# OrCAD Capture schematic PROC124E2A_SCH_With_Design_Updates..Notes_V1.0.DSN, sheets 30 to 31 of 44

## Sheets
30 29. JTAG 20 PIN cTI CONNECTOR: size C; title: JTAG 20 PIN cTI CONNECTOR
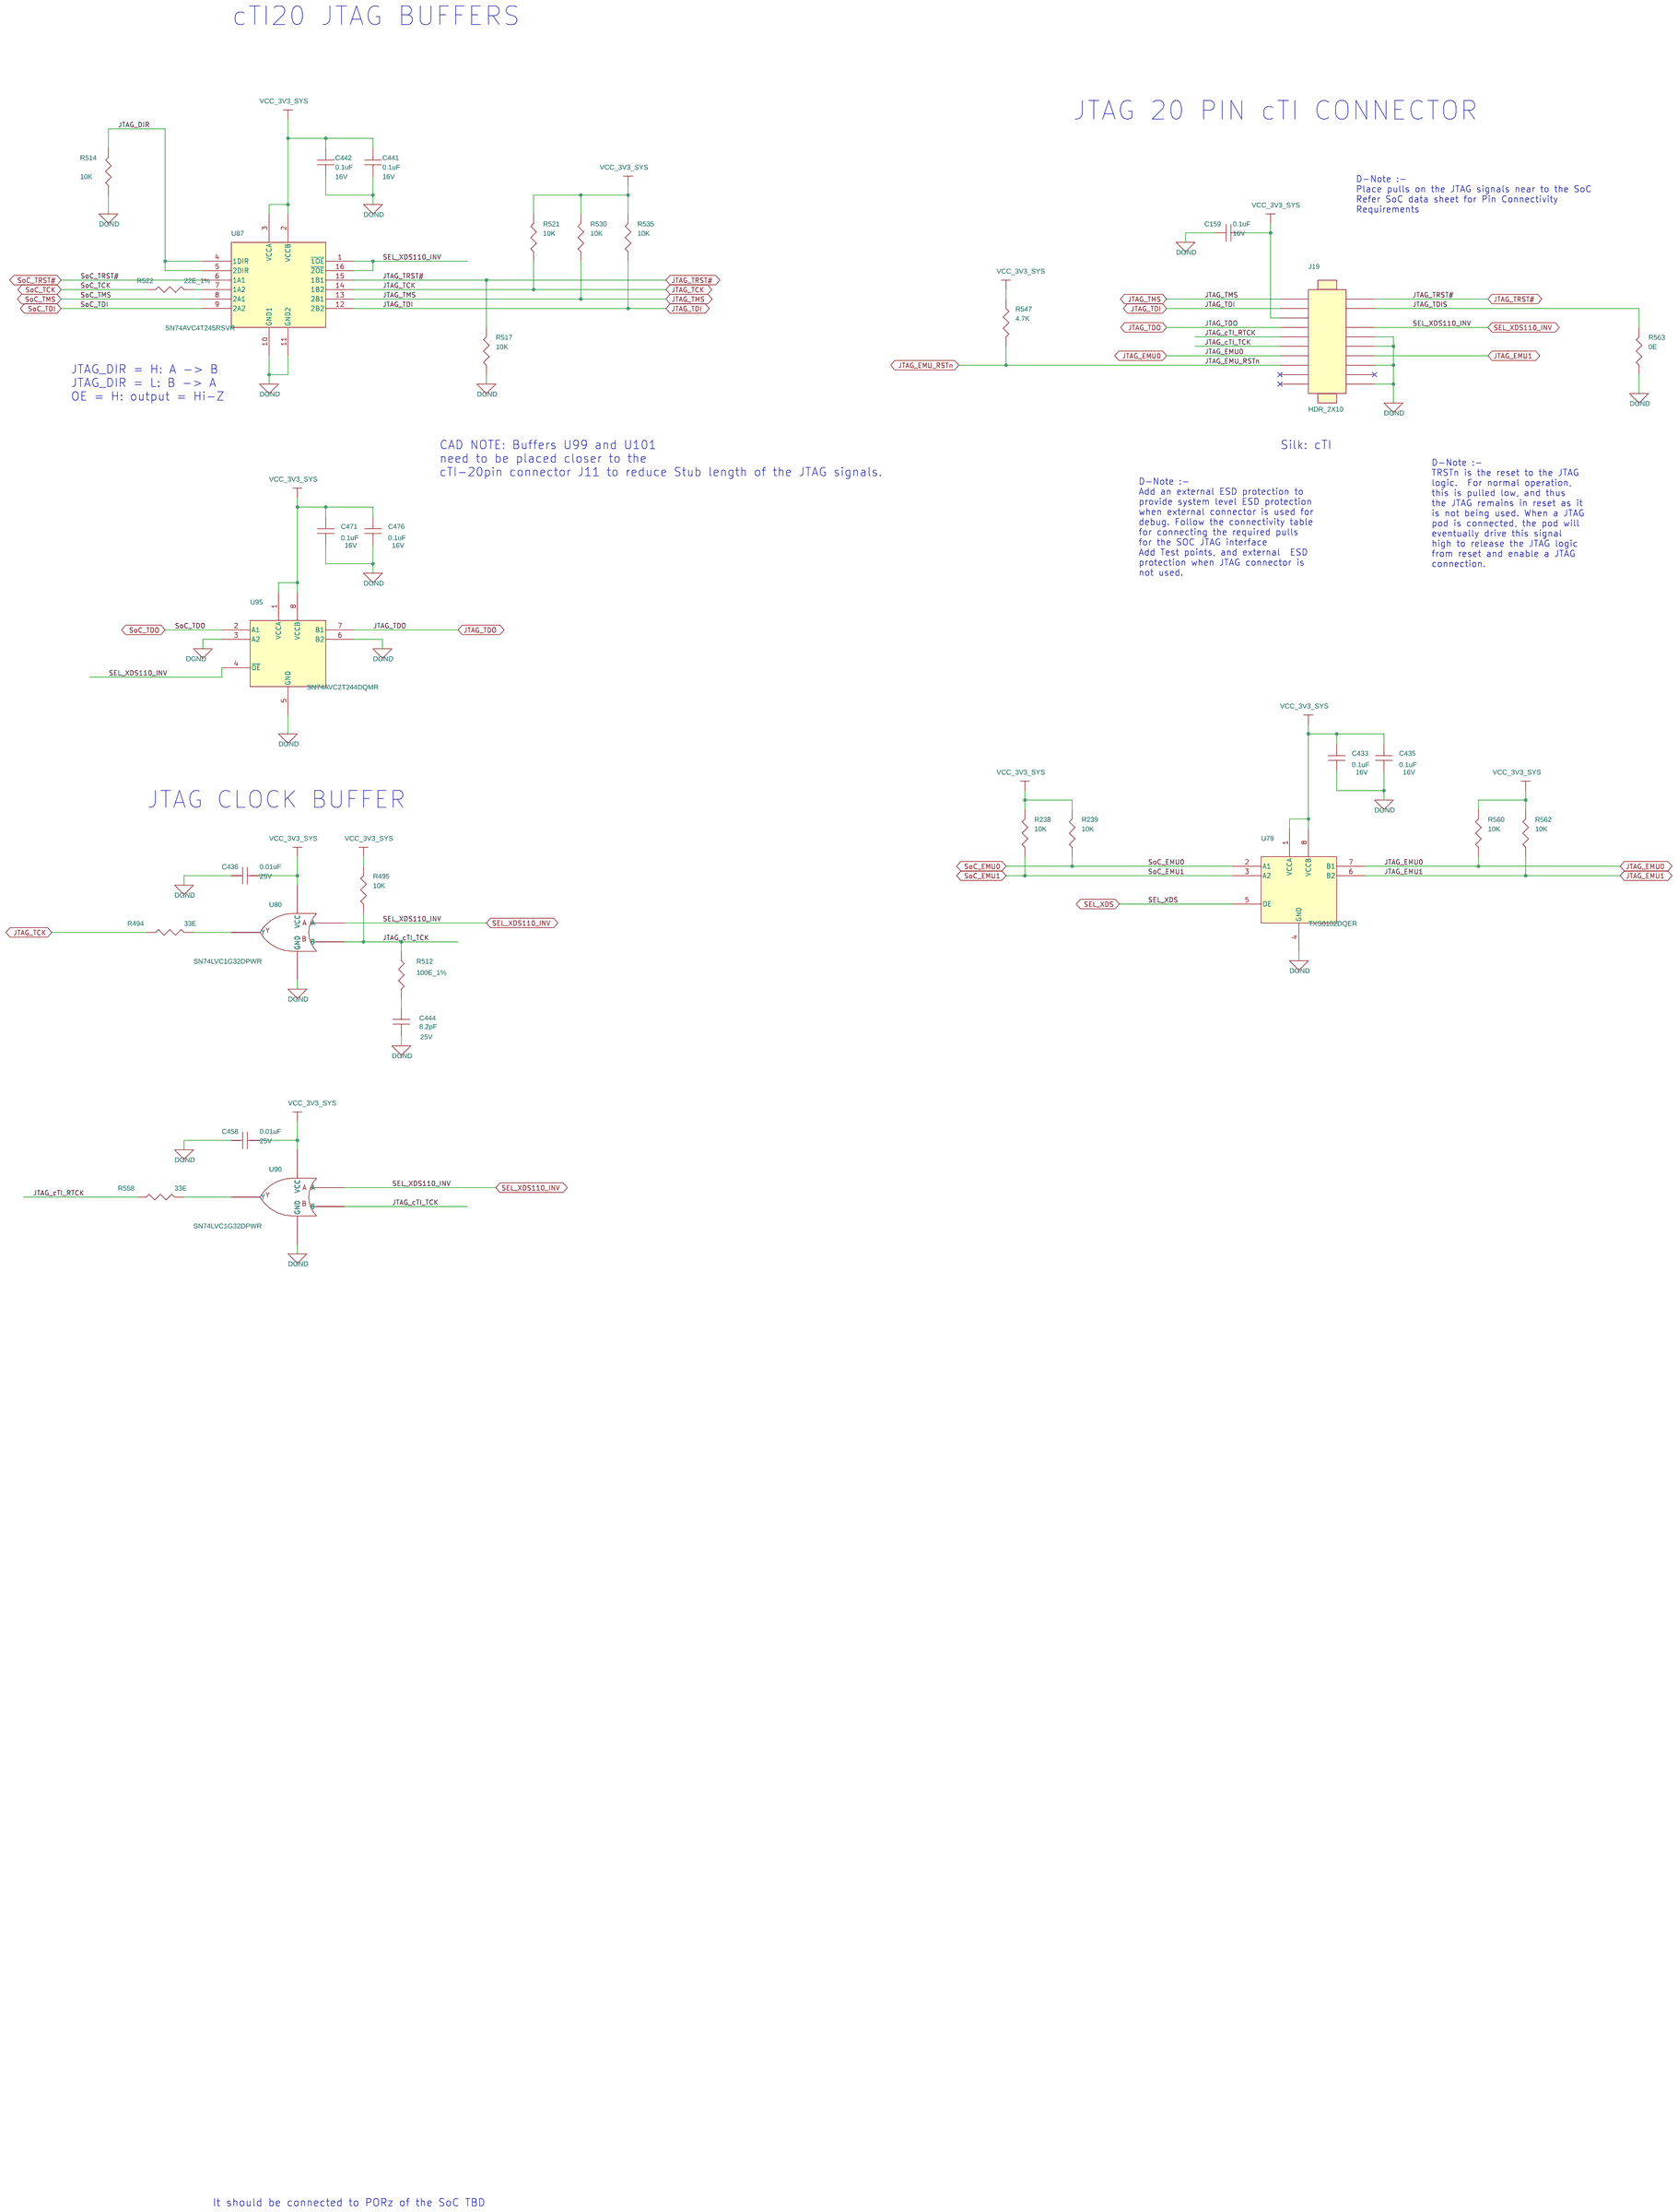
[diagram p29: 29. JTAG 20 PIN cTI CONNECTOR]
31 30. FT4232 UART TO USB BRIDGE: size C; title: FT4232 UART TO USB BRIDGE
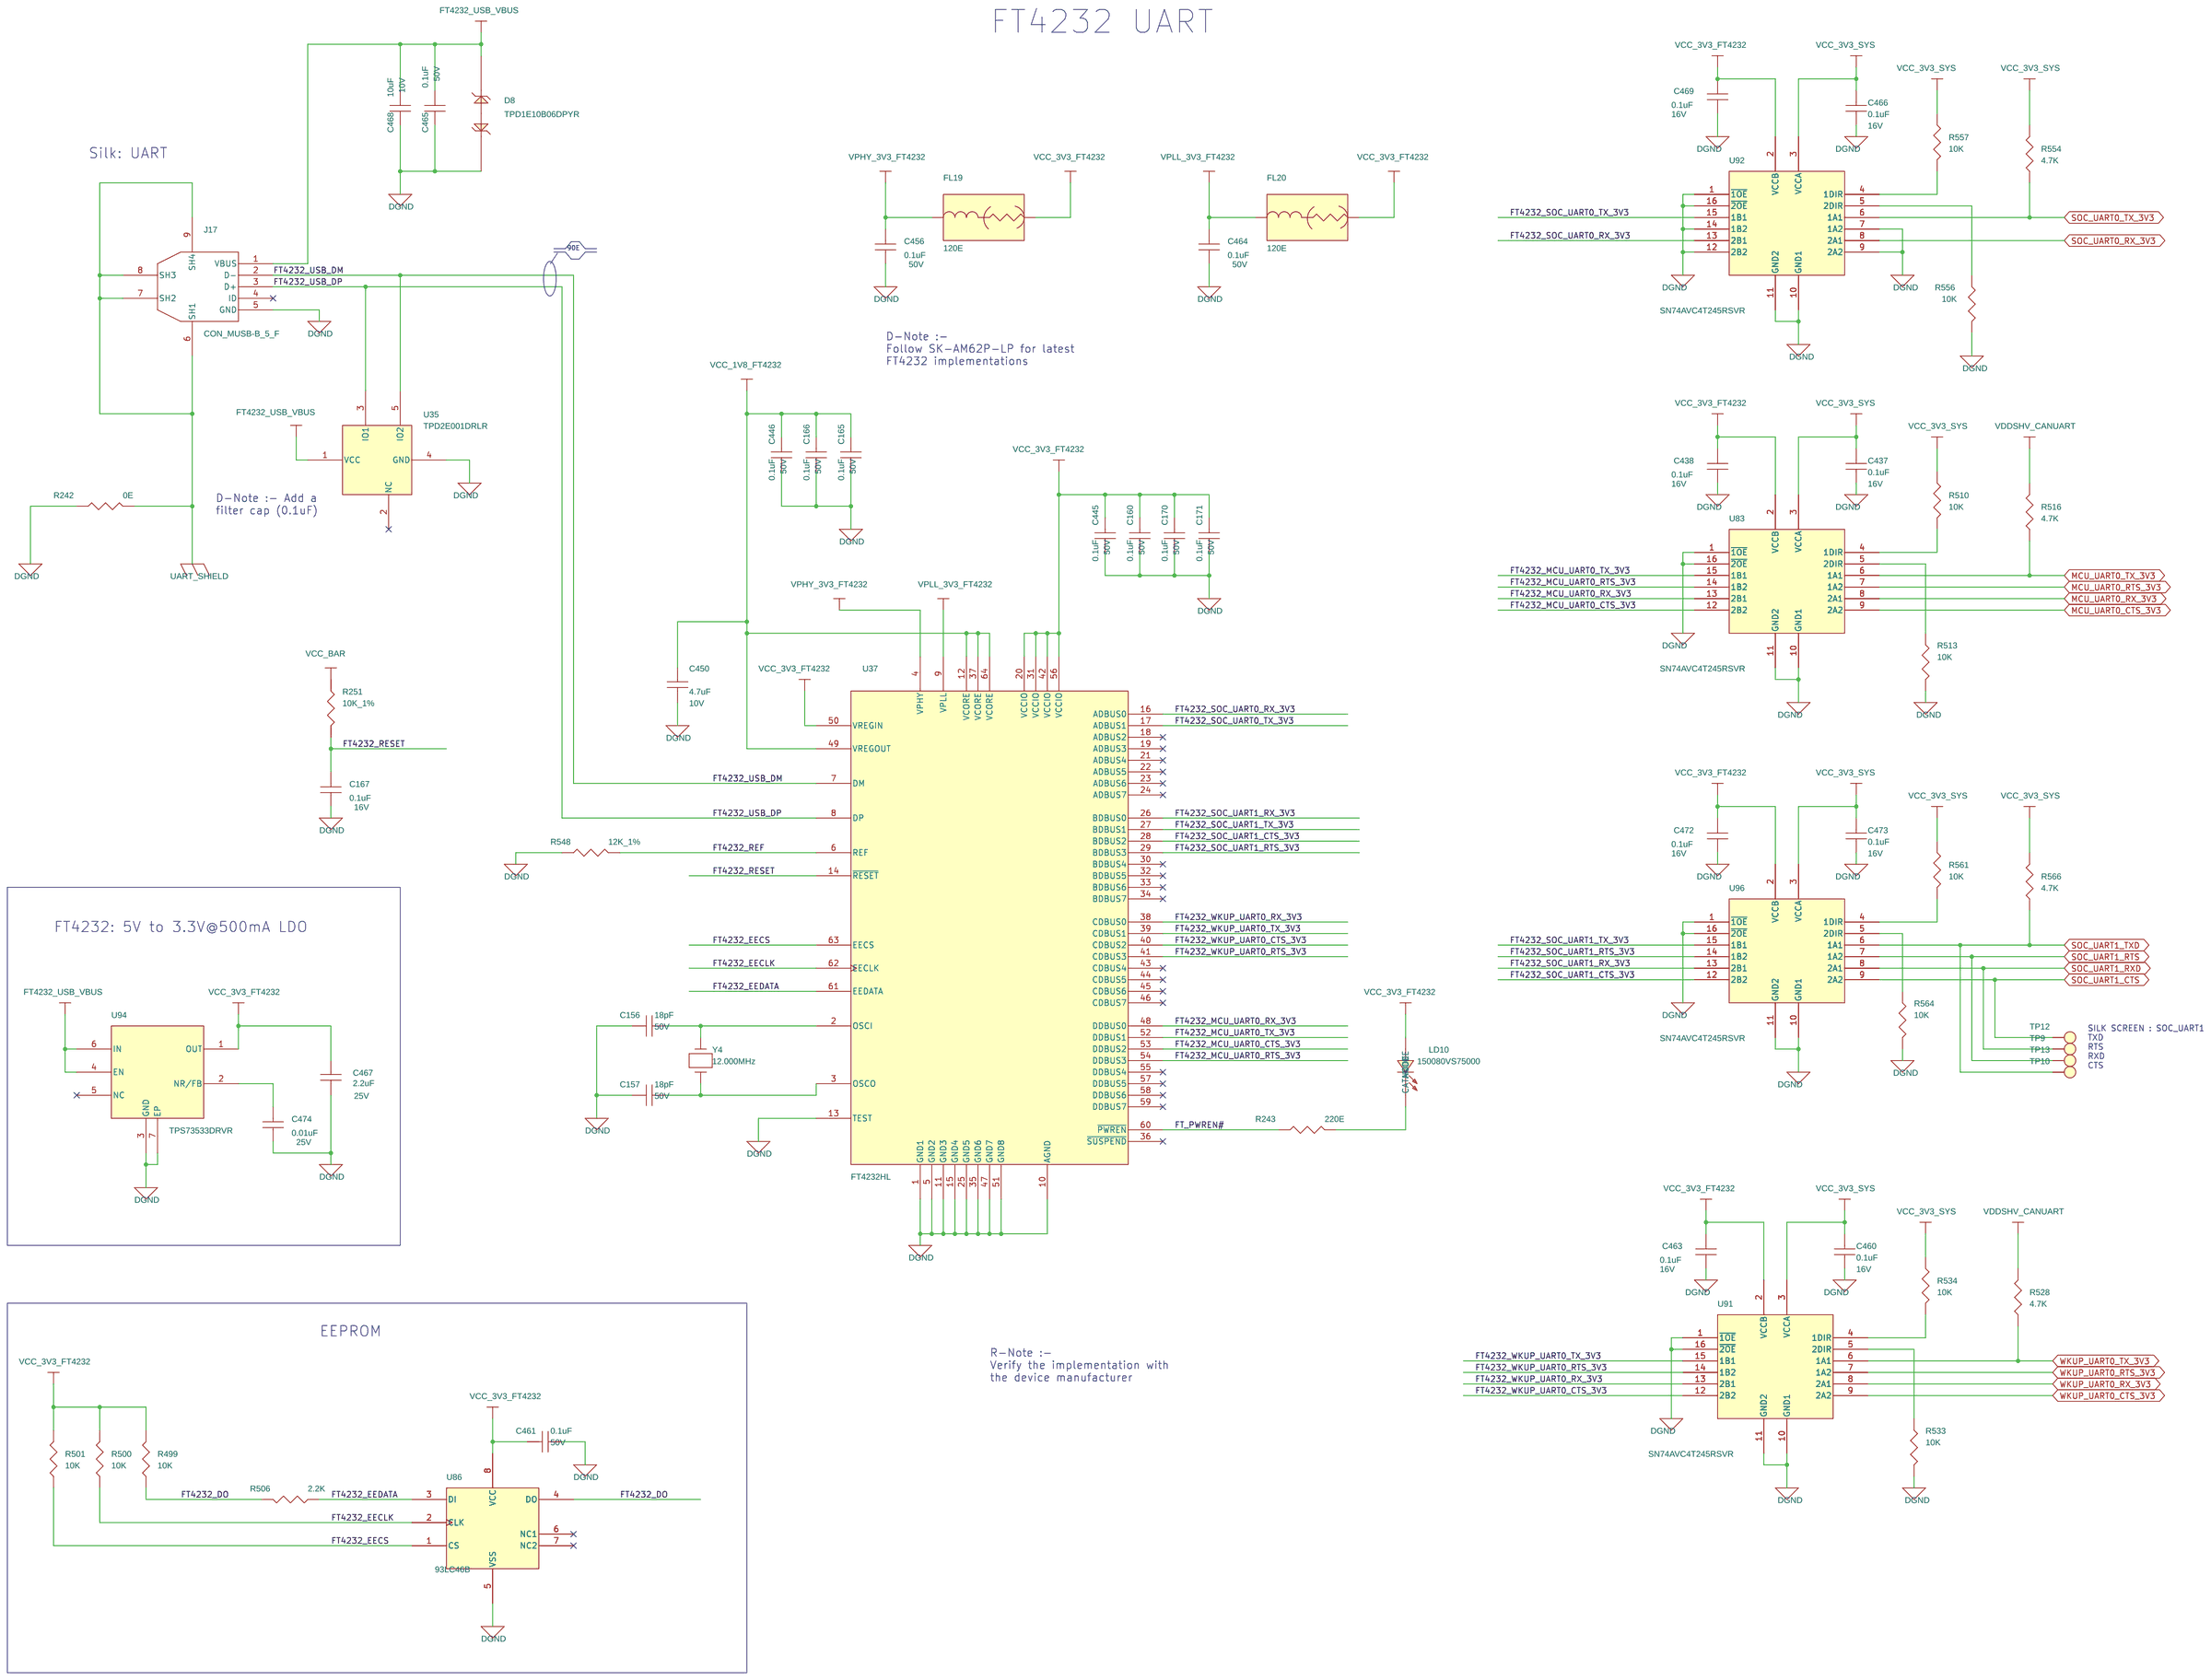
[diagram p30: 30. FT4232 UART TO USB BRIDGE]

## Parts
sheet 29. JTAG 20 PIN cTI CONNECTOR
C159  0.1uF  [CAP0201_0-5]
C433  0.1uF  [CAP0201_0-5]
C435  0.1uF  [CAP0201_0-5]
C436  0.01uF  [CAP0201_0-5]
C441  0.1uF  [CAP0201_0-5]
C442  0.1uF  [CAP0201_0-5]
C444  8.2pF  [CAP0201_0-5]
C458  0.01uF  [CAP0201_0-5]
C471  0.1uF  [CAP0201_0-5]
C476  0.1uF  [CAP0201_0-5]
J19  HDR_2X10  [HDR_2X10_FTR-110-51-D-06_S_S_8-7]
R238  10K  [RES0201_0-5]
R239  10K  [RES0201_0-5]
R494  33E  [RES0201_0-5]
R495  10K  [RES0201_0-5]
R512  100E_1%  [RES0402_0-5]
R514  10K  [RES0201_0-5]
R517  10K  [RES0201_0-5]
R521  10K  [RES0201_0-5]
R522  22E_1%  [RES0201_0-5]
R530  10K  [RES0201_0-5]
R535  10K  [RES0201_0-5]
R547  4.7K  [RES0201_0-5]
R558  33E  [RES0201_0-5]
R560  10K  [RES0201_0-5]
R562  10K  [RES0201_0-5]
R563  0E  [RES0201_0-5]
U79  TXS0102DQER  [X2SON8_TXS0102_40X60_0-4]
U80  SN74LVC1G32DPWR  [X2SON5_TLV7021_30X30_0-4]
U87  SN74AVC4T245RSVR  [UQFN16_TMUX1574_70X100_0-6]
U90  SN74LVC1G32DPWR  [X2SON5_TLV7021_30X30_0-4]
U95  SN74AVC2T244DQMR  [X2SON8_15-74_70X50]
sheet 30. FT4232 UART TO USB BRIDGE
C156  18pF  [CAP0402_0-75]
C157  18pF  [CAP0402_0-75]
C160  0.1uF  [CAP0402_0-75]
C165  0.1uF  [CAP0402_0-75]
C166  0.1uF  [CAP0402_0-75]
C167  0.1uF  [CAP0201_0-5]
C170  0.1uF  [CAP0402_0-75]
C171  0.1uF  [CAP0402_0-75]
C437  0.1uF  [CAP0201_0-5]
C438  0.1uF  [CAP0201_0-5]
C445  0.1uF  [CAP0402_0-75]
C446  0.1uF  [CAP0402_0-75]
C450  4.7uF  [CAP0402_0-75]
C456  0.1uF  [CAP0402_0-75]
C460  0.1uF  [CAP0201_0-5]
C461  0.1uF  [CAP0402_0-75]
C463  0.1uF  [CAP0201_0-5]
C464  0.1uF  [CAP0402_0-75]
C465  0.1uF  [CAP0402_0-75]
C466  0.1uF  [CAP0201_0-5]
C467  2.2uF  [CAP0402_0-75]
C468  10uF  [CAP0402_0-75]
C469  0.1uF  [CAP0201_0-5]
C472  0.1uF  [CAP0201_0-5]
C473  0.1uF  [CAP0201_0-5]
C474  0.01uF  [CAP0201_0-5]
D8  TPD1E10B06DPYR  [DIO_DFN0402_0-5]
FL19  120E  [EMIFIL_BLM15A_0402_0-6]
FL20  120E  [EMIFIL_BLM15A_0402_0-6]
J17  CON_MUSB-B_5_F  [CON_MUSBB5_629105150521_S_R_S_2-7]
LD10  150080VS75000  [LED_150080VS75000_80X50_SMD_0-8]
R242  0E  [RES0805_0-75]
R243  220E  [RES0402_0-5]
R251  10K_1%  [RES0201_0-5]
R499  10K  [RES0201_0-5]
R500  10K  [RES0201_0-5]
R501  10K  [RES0201_0-5]
R506  2.2K  [RES0201_0-5]
R510  10K  [RES0201_0-5]
R513  10K  [RES0201_0-5]
R516  4.7K  [RES0201_0-5]
R528  4.7K  [RES0201_0-5]
R533  10K  [RES0201_0-5]
R534  10K  [RES0201_0-5]
R548  12K_1%  [RES0402_0-5]
R554  4.7K  [RES0201_0-5]
R556  10K  [RES0201_0-5]
R557  10K  [RES0201_0-5]
R561  10K  [RES0201_0-5]
R564  10K  [RES0201_0-5]
R566  4.7K  [RES0201_0-5]
TP9  TP20_SMD  [TP20_SMD]
TP10  TP20_SMD  [TP20_SMD]
TP12  TP20_SMD  [TP20_SMD]
TP13  TP20_SMD  [TP20_SMD]
U35  TPD2E001DRLR  [SOT553-5_0-6]
U37  FT4232HL  [LQFP64_19-68_390X390_1-6]
U83  SN74AVC4T245RSVR  [UQFN16_TMUX1574_70X100_0-6]
U86  93LC46B  [MSOP8_25-59_125X125_1-1]
U91  SN74AVC4T245RSVR  [UQFN16_TMUX1574_70X100_0-6]
U92  SN74AVC4T245RSVR  [UQFN16_TMUX1574_70X100_0-6]
U94  TPS73533DRVR  [SON6_25-59_85X85]
U96  SN74AVC4T245RSVR  [UQFN16_TMUX1574_70X100_0-6]
Y4  12.000MHz  [XTAL_ABM3_205X130_SMD_1-4]

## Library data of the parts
C159 C167 C433 C435 C437 C438 C441 C442 C460 C463 C466 C469 C471-C473 C476 = CAP: CAP CERAMIC 0.1uF 16V 10% X5R 0201; Alt_Mfr_name: YAGEO AMERICA; Alt_Mfr_part_number: CC0402KRX5R8BB104; Chkd/date: MANIRAJA/230118; Crtd /date: MANIRAJA/230118; Custom_Duty: 15%; Customs_HS_Code: 85322990; Distributor_name: DIGIKEY; Distributor_part_number: 490-14305-1-ND; Footprint Path: Y:\MIS_DATABASE\Library\ALTIUM_TOOL\PCB_FOOTPRINTS\Altium_Footprint_Lib.PcbLib; Height: 0.33MM; Library Path: Y:\MIS_DATABASE\Library\ALTIUM_TOOL\SCHEMATICS_PARTS\MS_DISCRETE_Library.schlib; Mfr_name: MURATA; Mfr_part_number: GRM033R61C104KE14D; Mistral Part No: 120009030072-R; Package: 0201; Part_type: CAPACITORS\CERAMIC; Project: TI_MAXIE_CPB; RoHS: RoHS; Temperature: -55°C+85°C; Tolerance: 10%; Voltage: 16V; Wattage: NA; Weight: 0.33mg; Datasheet: Y:\MIS_DATABASE\DATASHEETS\CAPACITORS\GRM033R61C104KE14.PDF
C436 C458 C474 = CAP: CAP CERAMIC 0.01uF 25V 10% X5R 0201; Chkd/date: MANIRAJA/230118; Crtd /date: MANIRAJA/230118; Custom_Duty: 15%; Customs_HS_Code: 85322990; Distributor_name: DIGIKEY; Distributor_part_number: GRM033R61E103KA12J-ND; Footprint Path: Y:\MIS_DATABASE\Library\ALTIUM_TOOL\PCB_FOOTPRINTS\Altium_Footprint_Lib.PcbLib; Height: 0.33MM; Library Path: Y:\MIS_DATABASE\Library\ALTIUM_TOOL\SCHEMATICS_PARTS\MS_DISCRETE_Library.schlib; Mfr_name: MURATA; Mfr_part_number: GRM033R61E103KA12J; Mistral Part No: 120018010007-R; Package: 0201; Part_type: CAPACITORS\CERAMIC; Project: TI_MAXIE_CPB; RoHS: RoHS; Temperature: -55°C+85°C; Tolerance: 10%; Voltage: 25V; Wattage: NA; Weight: 0.33mg; Datasheet: Y:\MIS_DATABASE\DATASHEETS\CAPACITORS\GRM033R61E103KA12.PDF
C444 = CAP: CAP CERAMIC 8.2pF 25V 0.5pF C0G(NP0) 0201; Chkd/date: MANIRAJA/121020; Crtd /date: ALVY/091020; Custom_Duty: 15%; Customs_HS_Code: 85322990; Distributor_name: DIGIKEY; Distributor_part_number: 490-3140-1-ND; Footprint Path: Y:\MIS_DATABASE\Library\ALTIUM_TOOL\PCB_FOOTPRINTS\Altium_Footprint_Lib.PcbLib; Height: 0.33MM; Library Path: Y:\MIS_DATABASE\Library\ALTIUM_TOOL\SCHEMATICS_PARTS\MS_DISCRETE_Library.schlib; Mfr_name: MURATA; Mfr_part_number: GRM0335C1E8R2DA01D; Mistral Part No: 120020100018-R; Package: 0201; Part_type: CAPACITORS\CERAMIC; Project: AM64X_SKEVM; RoHS: RoHS; Temperature: -55°C+125°C; Tolerance: 0.5pF%; Voltage: 25V; Wattage: NA; Weight: 0.33mg; Datasheet: Y:\MIS_DATABASE\DATASHEETS\CAPACITORS\GRM0335C1E8R2DA01.PDF
J19 = HEADER_10X2_FTR-06: CON HDR 2X10 1.27MM PITCH ST SMD; Chkd/date: MANIRAJA/031218; Crtd /date: CHAITHANYA/050811; Custom_Duty: 24%; Customs_HS_Code: 85369090; Distributor_name: DIGIKEY; Distributor_part_number: SAM8792-ND; Footprint Path: Y:\MIS_DATABASE\Library\ALTIUM_TOOL\PCB_FOOTPRINTS\Altium_Footprint_Lib.PcbLib; Height: 8.67MM; Library Path: Y:\MIS_DATABASE\Library\ALTIUM_TOOL\SCHEMATICS_PARTS\MS_CONNECTOR_Library.schlib; Mfr_name: SAMTEC; Mfr_part_number: FTR-110-51-S-D-06; Mistral Part No: 150011090001-R; Package: SMD; Part_type: CONNECTOR\HEADERS; Project: GEMYC; RoHS: RoHS; Temperature: -55°C+125°C; Tolerance: NA; Voltage: NA; Wattage: NA; Weight: NA; Datasheet: Y:\MIS_DATABASE\DATASHEETS\CONNECTORS\FTR-D-SER.PDF
R238 R239 R495 R499-R501 R510 R513 R514 R517 R521 R530 R533-R535 R556 R557 R560-R562 R564 = RESISTOR: RES 10K 1/20W 5% 0201; Chkd/date: MANIRAJA/050517; Crtd /date: MANIRAJA/050517; Custom_Duty: 15%; Customs_HS_Code: 85332119; Distributor_name: DIGIKEY; Distributor_part_number: 311-10KNCT-ND; Footprint Path: Y:\MIS_DATABASE\Library\ALTIUM_TOOL\PCB_FOOTPRINTS\Altium_Footprint_Lib.PcbLib; Height: 0.26MM; Library Path: Y:\MIS_DATABASE\Library\ALTIUM_TOOL\SCHEMATICS_PARTS\MS_DISCRETE_Library.schlib; Mfr_name: YAGEO AMERICA; Mfr_part_number: RC0201JR-0710KL; Mistral Part No: 110010070051-R; Package: 0201; Part_type: RESISTORS\FIXED; Project: GOLDEN-I LITE; RoHS: RoHS; Temperature: -55°C+125°C; Tolerance: 5%; Voltage: NA; Wattage: 1/20W; Weight: 0.17mg; Datasheet: Y:\MIS_DATABASE\DATASHEETS\RESISTORS\RCXXXXL-SER_MAR18.PDF
R494 R558 = RESISTOR: RES 33E 1/20W 5% 0201; Chkd/date: ALVY/070422; Crtd /date: TAMILARASU/070422; Custom_Duty: 15%; Customs_HS_Code: 85332119; Distributor_name: DIGIKEY; Distributor_part_number: P123303CT-ND; Footprint Path: Y:\MIS_DATABASE\Library\ALTIUM_TOOL\PCB_FOOTPRINTS\Altium_Footprint_Lib.PcbLib; Height: 0.26MM; Library Path: Y:\MIS_DATABASE\Library\ALTIUM_TOOL\SCHEMATICS_PARTS\MS_DISCRETE_Library.schlib; Mfr_name: PANASONIC-ECG; Mfr_part_number: ERJ-1GNJ330C; Mistral Part No: 110010070052-R; Package: 0201; Part_type: RESISTORS\FIXED; Project: TI_AM62x_SKEVM_BRD; RoHS: RoHS; Temperature: -55°C+125°C; Tolerance: 5%; Voltage: NA; Wattage: 1/20W; Weight: 0.15mg; Datasheet: Y:\MIS_DATABASE\DATASHEETS\RESISTORS\PAN-ERJSER_NOV17.PDF
R512 = RESISTOR: RES 100E 1/16W 1% 0402; Chkd/date: MANIRAJA/060318; Crtd /date: NAVEED/220714; Custom_Duty: 15%; Customs_HS_Code: 85332119; Distributor_name: DIGIKEY; Distributor_part_number: 311-100LRCT-ND; Footprint Path: Y:\MIS_DATABASE\Library\ALTIUM_TOOL\PCB_FOOTPRINTS\Altium_Footprint_Lib.PcbLib; Height: 0.40MM; Library Path: Y:\MIS_DATABASE\Library\ALTIUM_TOOL\SCHEMATICS_PARTS\MS_DISCRETE_Library.schlib; Mfr_name: YAGEO AMERICA; Mfr_part_number: RC0402FR-07100RL; Mistral Part No: 110014070015-R; Package: 0402; Part_type: RESISTORS\FIXED; Project: DLRU; RoHS: RoHS; Temperature: -55°C+155°C; Tolerance: 1%; Voltage: NA; Wattage: 1/16W; Weight: 0.65mg; Datasheet: Y:\MIS_DATABASE\DATASHEETS\RESISTORS\RCXXXXL-SER_MAR18.PDF
R522 = RESISTOR: RES 22E 1/20W 1% 0201; Chkd/date: PRAVEEN/080922; Crtd /date: TAMILARASU/080922; Custom_Duty: 15%; Customs_HS_Code: 85332119; Distributor_name: DIGIKEY; Distributor_part_number: P122843CT-ND; Footprint Path: Y:\MIS_DATABASE\Library\ALTIUM_TOOL\PCB_FOOTPRINTS\Altium_Footprint_Lib.PcbLib; Height: 0.26MM; Library Path: Y:\MIS_DATABASE\Library\ALTIUM_TOOL\SCHEMATICS_PARTS\MS_DISCRETE_Library.schlib; Mfr_name: PANASONIC-ECG; Mfr_part_number: ERJ-1GNF22R0C; Mistral Part No: 110022090007-R; Package: 0201; Part_type: RESISTORS\FIXED; Project: SK AM62Q LP EVM BRD; RoHS: RoHS; Temperature: -55°C+125°C; Tolerance: 1%; Voltage: NA; Wattage: 1/20W; Weight: 0.15mg; Datasheet: Y:\MIS_DATABASE\DATASHEETS\RESISTORS\PAN-ERJSER_NOV17.PDF
R516 R528 R547 R554 R566 = RESISTOR: RES 4.7K 1/20W 5% 0201; Chkd/date: MANIRAJA/200921; Crtd /date: ALVY/200921; Custom_Duty: 15%; Customs_HS_Code: 85332119; Distributor_name: DIGIKEY; Distributor_part_number: 311-4.7KNCT-ND; Footprint Path: Y:\MIS_DATABASE\Library\ALTIUM_TOOL\PCB_FOOTPRINTS\Altium_Footprint_Lib.PcbLib; Height: 0.26MM; Library Path: Y:\MIS_DATABASE\Library\ALTIUM_TOOL\SCHEMATICS_PARTS\MS_DISCRETE_Library.schlib; Mfr_name: YAGEO AMERICA; Mfr_part_number: RC0201JR-074K7L; Mistral Part No: 110021090007-R; Package: 0201; Part_type: RESISTORS\FIXED; Project: TI_AM62x SKEVM_BRD; RoHS: RoHS; Temperature: -55°C+125°C; Tolerance: 5%; Voltage: NA; Wattage: 1/20W; Weight: 0.17mg; Datasheet: Y:\MIS_DATABASE\DATASHEETS\RESISTORS\RCXXXXL-SER_MAR18.PDF
R563 = RESISTOR: RES 0E 1/20W 5% 0201; Chkd/date: NAVEED/301214; Crtd /date: MUDDU/120710; Custom_Duty: 15%; Customs_HS_Code: 85332119; Distributor_name: DIGIKEY; Distributor_part_number: 311-0.0NCT-ND; Footprint Path: Y:\MIS_DATABASE\Library\ALTIUM_TOOL\PCB_FOOTPRINTS\Altium_Footprint_Lib.PcbLib; Height: 0.26MM; Library Path: Y:\MIS_DATABASE\Library\ALTIUM_TOOL\SCHEMATICS_PARTS\MS_DISCRETE_Library.schlib; Mfr_name: YAGEO AMERICA; Mfr_part_number: RC0201JR-070RL; Mistral Part No: 110010070067-R; Package: 0201; Part_type: RESISTORS\FIXED; Project: PB_BUGBASE; RoHS: RoHS; Temperature: -55°C+125°C; Tolerance: 5%; Voltage: NA; Wattage: 1/20W; Weight: 0.17mg; Datasheet: Y:\MIS_DATABASE\DATASHEETS\RESISTORS\RCXXXXL-SER_MAR18.PDF
U79 = TXS0102DQX_SON8: IC 2-BIT BI-DIR VOLTAGE-LEVEL TRANSLATOR FOR OPEN-DRAIN AND PUSH-PULL X2SON8; Chkd/date: MANIRAJA/010719; Crtd /date: CHAITHANYA230512; Custom_Duty: 15%; Customs_HS_Code: 85423100; Distributor_name: DIGIKEY; Distributor_part_number: 296-28368-1-ND; Footprint Path: Y:\MIS_DATABASE\Library\ALTIUM_TOOL\PCB_FOOTPRINTS\Altium_Footprint_Lib.PcbLib; Height: 0.40MM; Library Path: Y:\MIS_DATABASE\Library\ALTIUM_TOOL\SCHEMATICS_PARTS\MS_MISCINTERFACE_Library.schlib; Mfr_name: TEXAS INSTRUMENTS; Mistral Part No: 141012050010-R; Package: X2SON8; Part_type: ICS\INTERFACE\LEVEL TRANSLATOR; Project: GEN_3-8_DB; RoHS: RoHS; Temperature: -40°C+85°C; Tolerance: NA; Voltage: NA; Wattage: NA; Weight: 1.2mg; Datasheet: Y:\MIS_DATABASE\DATASHEETS\ICS\INTERFACE\TXS0102-SER.PDF
U80 U90 = SN74LVC1G32_X2SON5: IC SINGLE 2-INPUT POSITIVE-OR GATE X2SON5; Chkd/date: MANIRAJA/141020; Crtd /date: ALVY/131020; Custom_Duty: 15%; Customs_HS_Code: 85423100; Distributor_name: DIGIKEY; Distributor_part_number: 296-SN74LVC1G32DPWRCT-ND; Footprint Path: Y:\MIS_DATABASE\Library\ALTIUM_TOOL\PCB_FOOTPRINTS\Altium_Footprint_Lib.PcbLib; Height: 0.40MM; Library Path: Y:\MIS_DATABASE\Library\ALTIUM_TOOL\SCHEMATICS_PARTS\MS_GATE_Library.schlib; Mfr_name: TEXAS INSTRUMENTS; Mistral Part No: 141020100011-R; Package: X2SON5; Part_type: ICS\DIGITAL\GATES; Project: AM64X_SKEVM; RoHS: RoHS; Temperature: -40°C+125°C; Tolerance: NA; Voltage: NA; Wattage: NA; Weight: 0.6mg; Datasheet: Y:\MIS_DATABASE\DATASHEETS\ICS\DIGITAL\GATES\SN74LVC1G32XX.PDF
U83 U87 U91 U92 U96 = SN74AVC4T245RSV_UQFN16: IC 2-BIT BUS TRANSCEIVER WITH CONFIGURABLE VOLTAGE TRANSLATION AND 3 STATE O/P UQFN16; Chkd/date: MANIRAJA/040520; Crtd /date: BAVISH/190411; Custom_Duty: 15%; Customs_HS_Code: 85423100; Distributor_name: DIGIKEY; Distributor_part_number: 296-24366-1-ND; Footprint Path: Y:\MIS_DATABASE\Library\ALTIUM_TOOL\PCB_FOOTPRINTS\Altium_Footprint_Lib.PcbLib; Height: 0.55MM; Library Path: Y:\MIS_DATABASE\Library\ALTIUM_TOOL\SCHEMATICS_PARTS\MS_BUSDRIVERTRANSCEIVER_Library.schlib; Mfr_name: TEXAS INSTRUMENTS; Mistral Part No: 141011040011-R; Package: UQFN16; Part_type: ICS\DIGITAL\BUSTRANSCEIVER; Project: HMC; RoHS: RoHS; Temperature: -40°C+85°C; Tolerance: NA; Voltage: NA; Wattage: NA; Weight: 41mg; Datasheet: Y:\MIS_DATABASE\DATASHEETS\ICS\DIGITAL\BUSTRANSCEIVER\SN74AVC4T245-SER.PDF
U95 = SN74AVC2T244DQMR_X2SON8: IC 2-BIT UNDIRECTIONAL VOLTAGE-LEVEL TRANSLATOR X2SON8; Chkd/date: VASANTHA/060516; Crtd /date: VASANTHA/030316; Customs_HS_Code: 15%; Distributor_name: DIGIKEY; Distributor_part_number: 296-29674-1-ND; Height: 0.40MM; Mfr_name: TEXAS INSTRUMENTS; Mistral Part No: 141016030002-R; Package: X2SON8; Part_type: ICS\INTERFACE\LEVEL TRANSLATOR; Pb-Free: 85423100; Project: OCTASIC_3600; RoHS: RoHS; Temperature: -40°C+85°C; Tolerance: NA; Voltage: NA; Wattage: NA; Weight: NA; Datasheet: Y:\MIS_DATABASE\DATASHEETS\ICS\INTERFACE\SN74AVC2T244.PDF
C156 C157 = CAP: CAP CERAMIC 18pF 50V 5% HI-Q C0G(NP0) 0402; Chkd/date: VASANTHA/030315; Crtd /date: NAVEED/271014; Custom_Duty: 15%; Customs_HS_Code: 85322990; Distributor_name: DIGIKEY; Distributor_part_number: 490-3119-1-ND; Footprint Path: Y:\MIS_DATABASE\Library\ALTIUM_TOOL\PCB_FOOTPRINTS\Altium_Footprint_Lib.PcbLib; Height: 0.55MM; Library Path: Y:\MIS_DATABASE\Library\ALTIUM_TOOL\SCHEMATICS_PARTS\MS_DISCRETE_Library.schlib; Mfr_name: MURATA; Mfr_part_number: GJM1555C1H180JB01D; Mistral Part No: 120014100019-R; Package: 0402; Part_type: CAPACITORS\CERAMIC; Project: DC_MIST_RDC; RoHS: RoHS; Temperature: -55°C+125°C; Tolerance: 5%; Voltage: 50V; Wattage: NA; Weight: 6mg; Datasheet: Y:\MIS_DATABASE\DATASHEETS\CAPACITORS\MURATA-GXX-SER_NOV17.PDF
C160 C165 C166 C170 C171 C445 C446 C456 C461 C464 C465 = CAP: CAP CERAMIC 0.1uF 50V 10% X7R 0402; Alt_Mfr_name: YAGEO AMERICA; Alt_Mfr_part_number: CC0402KRX5R8BB104; Chkd/date: MANIRAJA/261020; Crtd /date: ALVY/211020; Custom_Duty: 15%; Customs_HS_Code: 85322990; Distributor_name: DIGIKEY; Distributor_part_number: 490-10700-1-ND; Footprint Path: Y:\MIS_DATABASE\Library\ALTIUM_TOOL\PCB_FOOTPRINTS\Altium_Footprint_Lib.PcbLib; Height: 0.55MM; Library Path: Y:\MIS_DATABASE\Library\ALTIUM_TOOL\SCHEMATICS_PARTS\MS_DISCRETE_Library.schlib; Mfr_name: MURATA; Mfr_part_number: GRM155R71H104KE14D; Mistral Part No: 120011100014-R; Package: 0402; Part_type: CAPACITORS\CERAMIC; Project: J7_CP; RoHS: RoHS; Temperature: -55°C+125°C; Tolerance: 10%; Voltage: 50V; Wattage: NA; Weight: 3.1mg; Datasheet: Y:\MIS_DATABASE\DATASHEETS\CAPACITORS\GRM155R71H104KE14.PDF
C450 = CAP: CAP CERAMIC 4.7uF 10V 20% X5R 0402; Chkd/date: MANIRAJA/110718; Crtd /date: ALVY/110718; Custom_Duty: 15%; Customs_HS_Code: 85322990; Distributor_name: DIGIKEY; Distributor_part_number: 490-14306-1-ND; Footprint Path: Y:\MIS_DATABASE\Library\ALTIUM_TOOL\PCB_FOOTPRINTS\Altium_Footprint_Lib.PcbLib; Height: 0.65MM; Library Path: Y:\MIS_DATABASE\Library\ALTIUM_TOOL\SCHEMATICS_PARTS\MS_DISCRETE_Library.schlib; Mfr_name: MURATA; Mfr_part_number: GRM155R61A475MEAAD; Mistral Part No: 120012060002-R; Package: 0402; Part_type: CAPACITORS\CERAMIC; Project: TI_J7SVB_PCIE_ADD-ON-CARD; RoHS: RoHS; Temperature: -55°C+85°C; Tolerance: 20%; Voltage: 10V; Wattage: NA; Weight: 14mg; Datasheet: Y:\MIS_DATABASE\DATASHEETS\CAPACITORS\GRM155R61A475MEAAD.PDF
C467 = CAP: CAP CERAMIC 2.2uF 25V 10% X5R 0402; Chkd/date: ALVY/010721; Crtd /date: MANIRAJA/010721; Custom_Duty: 15%; Customs_HS_Code: 85322990; Distributor_name: DIGIKEY; Distributor_part_number: 490-12703-1-ND; Footprint Path: Y:\MIS_DATABASE\Library\ALTIUM_TOOL\PCB_FOOTPRINTS\Altium_Footprint_Lib.PcbLib; Height: 0.70MM; Library Path: Y:\MIS_DATABASE\Library\ALTIUM_TOOL\SCHEMATICS_PARTS\MS_DISCRETE_Library.schlib; Mfr_name: MURATA; Mfr_part_number: GRM155R61E225KE11D; Mistral Part No: 120015120001-R; Package: 0402; Part_type: CAPACITORS\CERAMIC; Project: TI_AM263X_CC; RoHS: RoHS; Temperature: -55°C+85°C; Tolerance: 10%; Voltage: 25V; Wattage: NA; Weight: 1.5mg; Datasheet: Y:\MIS_DATABASE\DATASHEETS\CAPACITORS\GRM155R61E225KE11.PDF
C468 = CAP: CAP CERAMIC 10uF 10V 20% X5R 0402; Chkd/date: MANIRAJA/300520; Crtd /date: ALVY/260520; Custom_Duty: 15%; Customs_HS_Code: 85322990; Distributor_name: DIGIKEY; Distributor_part_number: 490-GRM155R61A106ME11DTR-ND; Footprint Path: Y:\MIS_DATABASE\Library\ALTIUM_TOOL\PCB_FOOTPRINTS\Altium_Footprint_Lib.PcbLib; Height: 0.55MM; Library Path: Y:\MIS_DATABASE\Library\ALTIUM_TOOL\SCHEMATICS_PARTS\MS_DISCRETE_Library.schlib; Mfr_name: MURATA; Mfr_part_number: GRM155R61A106ME11D; Mistral Part No: 120013110019-R; Package: 0402; Part_type: CAPACITORS\CERAMIC; Project: QCS610_NANOSOM; RoHS: RoHS; Temperature: -55°C+85°C; Tolerance: 20%; Voltage: 10V; Wattage: NA; Weight: 3.1mg; Datasheet: Y:\MIS_DATABASE\DATASHEETS\CAPACITORS\MURATA-GXX-SER_NOV17.PDF
D8 = DIODE_SOD323: DIODE 1CH ESD PROTECTION X1SON2; Chkd/date: MANIRAJA/040420; Crtd /date: VASANTHA/181114; Custom_Duty: 15%; Customs_HS_Code: 85423100; Distributor_name: DIGIKEY; Distributor_part_number: 296-30406-1-ND; Footprint Path: Y:\MIS_DATABASE\Library\ALTIUM_TOOL\PCB_FOOTPRINTS\Altium_Footprint_Lib.PcbLib; Height: 0.45MM; Library Path: Y:\MIS_DATABASE\Library\ALTIUM_TOOL\SCHEMATICS_PARTS\MS_DISCRETE_Library.schlib; Mfr_name: TEXAS INSTRUMENTS; Mistral Part No: 130014110022-R; Package: X1SON2; Part_type: DIODE; Project: GALILEO_EVM; RoHS: RoHS; Temperature: -40°C+125°C; Tolerance: NA; Voltage: NA; Wattage: NA; Weight: 1mg; Datasheet: Y:\MIS_DATABASE\DATASHEETS\ICS\INTERFACE\TPD1E10B06-SER.PDF
FL19 FL20 = EMIFILTER_IND: IND FERRITE BEAD CHIP 120E 2A 0402; Chkd/date: NAVEED/241114; Crtd /date: USMAN/170613; Custom_Duty: 24%; Customs_HS_Code: 85369090; Distributor_name: DIGIKEY; Distributor_part_number: 490-9656-1-ND; Footprint Path: Y:\MIS_DATABASE\Library\ALTIUM_TOOL\PCB_FOOTPRINTS\Altium_Footprint_Lib.PcbLib; Height: 0.55MM; Library Path: Y:\MIS_DATABASE\Library\ALTIUM_TOOL\SCHEMATICS_PARTS\MS_FILTER_Library.schlib; Mfr_name: MURATA; Mfr_part_number: BLM15PX121SN1D; Mistral Part No: 130013060022-R; Package: 0402; Part_type: INDUCTOR; Project: GEN_3-8; RoHS: RoHS; Temperature: -55°C+125°C; Tolerance: 25%; Voltage: NA; Wattage: NA; Weight: 1mg; Datasheet: Y:\MIS_DATABASE\DATASHEETS\DISCRETES\INDUCTORS\BLM15-SN1-SER.PDF
J17 = CON_USB_MINI-B: CON MICRO USB TYPE B 5POS FEMALE RT SMD; Chkd/date: MANIRAJA/150519; Crtd /date: ALVY/150519; Custom_Duty: 24%; Customs_HS_Code: 85369090; Distributor_name: DIGIKEY; Distributor_part_number: 732-5960-1-ND; Footprint Path: Y:\MIS_DATABASE\Library\ALTIUM_TOOL\PCB_FOOTPRINTS\Altium_Footprint_Lib.PcbLib; Height: 2.66MM; Library Path: Y:\MIS_DATABASE\Library\ALTIUM_TOOL\SCHEMATICS_PARTS\MS_CONNECTOR_Library.schlib; Mfr_name: WURTH ELECTRONICS; Mfr_part_number: 629105150521; Mistral Part No: 150019050015-R; Package: SMD; Part_type: CONNECTOR\USB; Project: NEXTNAV_ALT-STATION_ATE_BRD; RoHS: RoHS; Temperature: -40°C+85°C; Tolerance: NA; Voltage: NA; Wattage: NA; Weight: 360mg; Datasheet: Y:\MIS_DATABASE\DATASHEETS\CONNECTORS\629105150521.PDF
LD10 = DIODE_LED: DIODE LED BRIGHT GREEN SMD; Chkd/date: MANIRAJA/180820; Crtd /date: ALVY/180820; Custom_Duty: 24%; Customs_HS_Code: 85439000; Distributor_name: DIGIKEY; Distributor_part_number: 732-4986-1-ND; Footprint Path: Y:\MIS_DATABASE\Library\ALTIUM_TOOL\PCB_FOOTPRINTS\Altium_Footprint_Lib.PcbLib; Height: 0.80MM; Library Path: Y:\MIS_DATABASE\Library\ALTIUM_TOOL\SCHEMATICS_PARTS\MS_OPTO_Library.schlib; Mfr_name: WURTH ELECTRONICS; Mistral Part No: 130020080012-R; Package: SMD; Part_type: OPTO\LED; Project: AM64x_EVM_BRD; RoHS: RoHS; Temperature: -40°C+85°C; Tolerance: NA; Voltage: NA; Wattage: NA; Weight: 10mg; Datasheet: Y:\MIS_DATABASE\DATASHEETS\DISCRETES\LEDS\150080VS75000.PDF
R242 = RESISTOR: RES 0E 1/8W 5% 0805; Chkd/date: VASANTHA/130416; Crtd /date: JEBRAN/020316; Custom_Duty: 15%; Customs_HS_Code: 85332119; Distributor_name: DIGIKEY; Distributor_part_number: 311-0.0ARCT-ND; Footprint Path: Y:\MIS_DATABASE\Library\ALTIUM_TOOL\PCB_FOOTPRINTS\Altium_Footprint_Lib.PcbLib; Height: 0.60MM; Library Path: Y:\MIS_DATABASE\Library\ALTIUM_TOOL\SCHEMATICS_PARTS\MS_DISCRETE_Library.schlib; Mfr_name: YAGEO AMERICA; Mfr_part_number: RC0805JR-070RL; Mistral Part No: 110009030074-R; Package: 0805; Part_type: RESISTORS\FIXED; Project: ZK_BIOMETRIC; RoHS: RoHS; Temperature: -55°C+155°C; Tolerance: 5%; Voltage: NA; Wattage: 1/8W; Weight: 5.5mg; Datasheet: Y:\MIS_DATABASE\DATASHEETS\RESISTORS\RCXXXXL-SER_MAR18.PDF
R243 = RESISTOR: RES 220E 1/10W 5% 0402; Chkd/date: VASANTHA/291216; Crtd /date: GEETHA/260406; Custom_Duty: 15%; Customs_HS_Code: 85332119; Distributor_name: DIGIKEY; Distributor_part_number: P220JCT-ND; Footprint Path: Y:\MIS_DATABASE\Library\ALTIUM_TOOL\PCB_FOOTPRINTS\Altium_Footprint_Lib.PcbLib; Height: 0.40MM; Library Path: Y:\MIS_DATABASE\Library\ALTIUM_TOOL\SCHEMATICS_PARTS\MS_DISCRETE_Library.schlib; Mfr_name: PANASONIC-ECG; Mfr_part_number: ERJ-2GEJ221X; Mistral Part No: 110009030506-R; Package: 0402; Part_type: RESISTORS\FIXED; Project: RED EYE; RoHS: RoHS; Temperature: -55°C+155°C; Tolerance: 5%; Voltage: NA; Wattage: 1/10W; Weight: 0.8mg; Datasheet: Y:\MIS_DATABASE\DATASHEETS\RESISTORS\PAN-ERJSER_NOV17.PDF
R251 = RESISTOR: RES 10K 1/20W 1% 0201; Chkd/date: VASANTHA/270117; Crtd /date: MANIRAJA/270117; Custom_Duty: 15%; Customs_HS_Code: 85332119; Distributor_name: DIGIKEY; Distributor_part_number: 311-10.0KMCT-ND; Footprint Path: Y:\MIS_DATABASE\Library\ALTIUM_TOOL\PCB_FOOTPRINTS\Altium_Footprint_Lib.PcbLib; Height: 0.26MM; Library Path: Y:\MIS_DATABASE\Library\ALTIUM_TOOL\SCHEMATICS_PARTS\MS_DISCRETE_Library.schlib; Mfr_name: YAGEO AMERICA; Mfr_part_number: RC0201FR-0710KL; Mistral Part No: 110011040018-R; Package: 0201; Part_type: RESISTORS\FIXED; Project: GOLDEN-I LITE; RoHS: RoHS; Temperature: -55°C+125°C; Tolerance: 1%; Voltage: NA; Wattage: 1/20W; Weight: 0.17mg; Datasheet: Y:\MIS_DATABASE\DATASHEETS\RESISTORS\RCXXXXL-SER_MAR18.PDF
R506 = RESISTOR: RES 2.2K 1/20W 5% 0201; Chkd/date: MANIRAJA/310821; Crtd /date: ALVY/310821; Custom_Duty: 15%; Customs_HS_Code: 85332119; Distributor_name: DIGIKEY; Distributor_part_number: P123277CT-ND; Footprint Path: Y:\MIS_DATABASE\Library\ALTIUM_TOOL\PCB_FOOTPRINTS\Altium_Footprint_Lib.PcbLib; Height: 0.26MM; Library Path: Y:\MIS_DATABASE\Library\ALTIUM_TOOL\SCHEMATICS_PARTS\MS_DISCRETE_Library.schlib; Mfr_name: PANASONIC-ECG; Mfr_part_number: ERJ-1GNJ222C; Mistral Part No: 110009030427-R; Package: 0201; Part_type: RESISTORS\FIXED; Project: TI_AM335x SK_BRD; RoHS: RoHS; Temperature: -55°C+125°C; Tolerance: 5%; Voltage: NA; Wattage: 1/20W; Weight: 0.15mg; Datasheet: Y:\MIS_DATABASE\DATASHEETS\RESISTORS\PAN-ERJSER_NOV17.PDF
R548 = RESISTOR: RES 12K 1/10W 1% 0402; Chkd/date: VASANTHA/041215; Crtd /date: VASANTHA/041215; Custom_Duty: 15%; Customs_HS_Code: 85332119; Distributor_name: DIGIKEY; Distributor_part_number: P12.0KLCT-ND; Footprint Path: Y:\MIS_DATABASE\Library\ALTIUM_TOOL\PCB_FOOTPRINTS\Altium_Footprint_Lib.PcbLib; Height: 0.40MM; Library Path: Y:\MIS_DATABASE\Library\ALTIUM_TOOL\SCHEMATICS_PARTS\MS_DISCRETE_Library.schlib; Mfr_name: PANASONIC-ECG; Mfr_part_number: ERJ-2RKF1202X; Mistral Part No: 110019040053-R; Package: 0402; Part_type: RESISTORS\FIXED; Project: TI_C5545; RoHS: RoHS; Temperature: -55°C+155°C; Tolerance: 1%; Voltage: NA; Wattage: 1/10W; Weight: 0.8mg; Datasheet: Y:\MIS_DATABASE\DATASHEETS\RESISTORS\PAN-ERJSER_NOV17.PDF
TP9 TP10 TP12 TP13 = TESTPOINT: TESTPOINT CIR 20 SMD; Chkd/date: SHREESHAIL/171006; Crtd /date: MAZHAR/171006; Custom_Duty: NA; Customs_HS_Code: NA; Distributor_name: NA; Distributor_part_number: NA; Footprint Path: Y:\MIS_DATABASE\Library\ALTIUM_TOOL\PCB_FOOTPRINTS\Altium_Footprint_Lib.PcbLib; Height: NA; Library Path: Y:\MIS_DATABASE\Library\ALTIUM_TOOL\SCHEMATICS_PARTS\MS_DISCRETE_Library.schlib; MECHANICAL 3D STEP FILE: NA; Mfr_name: LOCAL; Mistral Part No: NA; Package: SMD; Project: BT MODULE_CSRBC04; RoHS: NA; Temperature: NA; Tolerance: NA; Voltage: NA; Wattage: NA; Weight: NA; Datasheet: NA
U35 = TPD2E001DRLR_SOT-5: IC ESD-PROTECTION DIODE ARRAYS SOT-5; Chkd/date: NAVEED/150714; Crtd /date: MUDDU/250510; Custom_Duty: 15%; Customs_HS_Code: 85423100; Distributor_name: DIGIKEY; Distributor_part_number: 296-21883-1-ND; Footprint Path: Y:\MIS_DATABASE\Library\ALTIUM_TOOL\PCB_FOOTPRINTS\Altium_Footprint_Lib.PcbLib; Height: 0.60MM; Library Path: Y:\MIS_DATABASE\Library\ALTIUM_TOOL\SCHEMATICS_PARTS\MS_FILTER_Library.schlib; Mfr_name: TEXAS INSTRUMENTS; Mistral Part No: 140110060007-R; Package: SOT-5; Part_type: ICS\ANALOG\ACTIVE FILTER; Project: CENTAURUS; RoHS: RoHS; Temperature: -40°C+85°C; Tolerance: NA; Voltage: NA; Wattage: NA; Weight: 2.8mg; Datasheet: Y:\MIS_DATABASE\DATASHEETS\ICS\MISC\TPD2E001DRLR.PDF
U37 = FT4232H_LQFP64: IC HIGH SPEED QUAD USB UART LQFP64; Chkd/date: MANIRAJA/110917; Crtd /date: VIJAYALAKSHMI/120813; Custom_Duty: 15%; Customs_HS_Code: 85423100; Distributor_name: DIGIKEY; Distributor_part_number: 768-1026-1-ND; Footprint Path: Y:\MIS_DATABASE\Library\ALTIUM_TOOL\PCB_FOOTPRINTS\Altium_Footprint_Lib.PcbLib; Height: 1.60MM; Library Path: Y:\MIS_DATABASE\Library\ALTIUM_TOOL\SCHEMATICS_PARTS\MS_COMBINATIONAL_Library.schlib; Mfr_name: FTDI; Mfr_part_number: FT4232HL-REEL; Mistral Part No: 141013080006-R; Package: LQFP64; Part_type: ICS\DIGITAL\PERIPHERAL; Project: DM37XX; RoHS: RoHS; Temperature: -40°C+85°C; Tolerance: NA; Voltage: NA; Wattage: NA; Weight: 342.7mg; Datasheet: Y:\MIS_DATABASE\DATASHEETS\ICS\DIGITAL\PERIPHERAL\FT4232HX.PDF
U86 = 93LC46B_MSOP8: IC 1K MICROWIRE COMPATIBLE SERIAL EEPROM MSOP8; Chkd/date: MANIRAJA/150218; Crtd /date: ALVY/150218; Custom_Duty: 15%; Customs_HS_Code: 85423100; Distributor_name: DIGIKEY; Distributor_part_number: 93LC46B-I/MS-ND; Footprint Path: Y:\MIS_DATABASE\Library\ALTIUM_TOOL\PCB_FOOTPRINTS\Altium_Footprint_Lib.PcbLib; Height: 1.10MM; Library Path: Y:\MIS_DATABASE\Library\ALTIUM_TOOL\SCHEMATICS_PARTS\MS_MISCMEMORY_Library.schlib; Mfr_name: MICROCHIP; Mfr_part_number: 93LC46B-I/MS; Mistral Part No: 141118020002-R; Package: MSOP8; Part_type: ICS\DIGITAL\MEMORY; Project: TI_MAXIE_CPB; RoHS: RoHS; Temperature: -40°C+85°C; Tolerance: NA; Voltage: NA; Wattage: NA; Weight: 140mg; Datasheet: Y:\MIS_DATABASE\DATASHEETS\ICS\MEMORY\93LC46B.PDF
U94 = TPS73501DRVR_SON6: IC 500mA LOW DROPOUT REGULATOR SON6; Chkd/date: VASANTHA/280915; Crtd /date: NAVEED/011014; Custom_Duty: 15%; Customs_HS_Code: 85423100; Distributor_name: DIGIKEY; Distributor_part_number: TPS73533DRVR-ND; Height: 0.80MM; Mfr_name: TEXAS INSTRUMENTS; Mistral Part No: 142014100001-R; Package: SON6; Part_type: ICS\POWER\VOLTAGE REGULATOR; Project: BLUETOOTH_WATCH; RoHS: RoHS; Temperature: -40°C+125°C; Tolerance: NA; Voltage: NA; Wattage: NA; Weight: NA; Datasheet: Y:\MIS_DATABASE\DATASHEETS\ICS\POWER\TPS735.PDF
Y4 = CRY: CRY 12.000MHz 18pF SMD; Chkd/date: MANIRAJA/310818; Crtd /date: MANIRAJA/310818; Custom_Duty: 24%; Customs_HS_Code: 85439000; Distributor_name: DIGIKEY; Distributor_part_number: CTX1170CT-ND; Footprint Path: Y:\MIS_DATABASE\Library\ALTIUM_TOOL\PCB_FOOTPRINTS\Altium_Footprint_Lib.PcbLib; Height: 1.35MM; Library Path: Y:\MIS_DATABASE\Library\ALTIUM_TOOL\SCHEMATICS_PARTS\MS_DISCRETE_Library.schlib; Mfr_name: CTS; Mfr_part_number: 445I23D12M00000; Mistral Part No: 130018080040-R; Package: SMD; Part_type: CRYSTAL; Project: TI_MAXIE_CPB; RoHS: RoHS; Temperature: -40°C+85°C; Tolerance: NA; Voltage: NA; Wattage: NA; Weight: 50mg; Datasheet: Y:\MIS_DATABASE\DATASHEETS\MISC\CRY_OSC\445.PDF

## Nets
DGND: C156.2 C157.2 C159.2 C160.1 C165.1 C166.1 C167.1 C170.1 C171.1 C433.1 C435.1 C436.1 C437.1 C438.1 C441.1 C442.1 C444.2 C445.1 C446.1 C450.2 C456.1 C458.1 C460.1 C461.1 C463.1 C464.1 C465.1 C466.1 C467.2 C468.1 C469.1 C471.1 C472.1 C473.1 C474.1 C476.1 D8.1 J17.5(GND) J19.10 J19.12 J19.16 J19.20 R242.1 R513.1 R514.1 R517.1 R533.1 R548.1 R556.1 R563.1 R564.1 U35.4(GND) U37.1(GND1) U37.5(GND2) U37.10(AGND) U37.11(GND3) U37.13(TEST) U37.15(GND4) U37.25(GND5) U37.35(GND6) U37.47(GND7) U37.51(GND8) U79.4(GND) U80.3(GND) U83.1(~{1OE}) U83.10(GND1) U83.11(GND2) U83.16(~{2OE}) U86.5(VSS) U87.10(GND1) U87.11(GND2) U90.3(GND) U91.1(~{1OE}) U91.10(GND1) U91.11(GND2) U91.16(~{2OE}) U92.1(~{1OE}) U92.7(1A2) U92.9(2A2) U92.10(GND1) U92.11(GND2) U92.12(2B2) U92.14(1B2) U92.16(~{2OE}) U94.3(GND) U94.7(EP) U95.3(A2) U95.5(GND) U95.6(B2) U96.1(~{1OE}) U96.10(GND1) U96.11(GND2) U96.16(~{2OE}) ; also on sheet 1 2 3 4 13 14 15 16 17 18 19 20 21 22 23 24 25 26 27 28 29 32 33 34 35 36 37 38 39 40 41 42 43
VCC_1V8_FT4232: C165.2 C166.2 C446.2 C450.1 U37.12(VCORE) U37.37(VCORE) U37.49(VREGOUT) U37.64(VCORE)
VCC_3V3_FT4232: C160.2 C170.2 C171.2 C438.2 C445.2 C461.2 C463.2 C467.1 C469.2 C472.2 FL19.2 FL20.2 LD10.2(ANODE) R499.2 R500.2 R501.2 U37.20(VCCIO) U37.31(VCCIO) U37.42(VCCIO) U37.50(VREGIN) U37.56(VCCIO) U83.2(VCCB) U86.8(VCC) U91.2(VCCB) U92.2(VCCB) U94.1(OUT) U96.2(VCCB)
VCC_3V3_SYS: C159.1 C433.2 C435.2 C436.2 C437.2 C441.2 C442.2 C458.2 C460.2 C466.2 C471.2 C473.2 C476.2 J19.5 R238.1 R239.1 R495.2 R510.2 R521.2 R530.2 R534.2 R535.2 R547.1 R554.1 R557.2 R560.1 R561.2 R562.1 R566.1 U79.1(VCCA) U79.8(VCCB) U80.5(VCC) U83.3(VCCA) U87.2(VCCB) U87.3(VCCA) U90.5(VCC) U91.3(VCCA) U92.3(VCCA) U95.1(VCCA) U95.8(VCCB) U96.3(VCCA) ; also on sheet 1 4 15 16 19 20 21 23 24 26 27 29 32 33 34 36 37 38 39 40 41 42 43
VDDSHV_CANUART: R516.1 R528.1 ; also on sheet 2 4 17 32
FT4232_DO: R499.1 R506.2 U86.4(DO)
FT4232_EECLK: R500.1 U37.62(EECLK) U86.2(CLK)
FT4232_EECS: R501.1 U37.63(EECS) U86.1(CS)
FT4232_EEDATA: R506.1 U37.61(EEDATA) U86.3(DI)
FT4232_MCU_UART0_CTS_3V3: U37.53(DDBUS2) U83.12(2B2)
FT4232_MCU_UART0_RTS_3V3: U37.54(DDBUS3) U83.14(1B2)
FT4232_MCU_UART0_RX_3V3: U37.48(DDBUS0) U83.13(2B1)
FT4232_MCU_UART0_TX_3V3: U37.52(DDBUS1) U83.15(1B1)
FT4232_REF: R548.2 U37.6(REF)
FT4232_RESET: C167.2 R251.1 U37.14(~{RESET})
FT4232_SOC_UART0_RX_3V3: U37.16(ADBUS0) U92.13(2B1)
FT4232_SOC_UART0_TX_3V3: U37.17(ADBUS1) U92.15(1B1)
FT4232_SOC_UART1_CTS_3V3: U37.28(BDBUS2) U96.12(2B2)
FT4232_SOC_UART1_RTS_3V3: U37.29(BDBUS3) U96.14(1B2)
FT4232_SOC_UART1_RX_3V3: U37.26(BDBUS0) U96.13(2B1)
FT4232_SOC_UART1_TX_3V3: U37.27(BDBUS1) U96.15(1B1)
FT4232_USB_DM: J17.2(D-) U35.5(IO2) U37.7(DM)
FT4232_USB_DP: J17.3(D+) U35.3(IO1) U37.8(DP)
FT4232_USB_VBUS: C465.2 C468.2 D8.2 J17.1(VBUS) U35.1(VCC) U94.4(EN) U94.6(IN)
FT4232_WKUP_UART0_CTS_3V3: U37.40(CDBUS2) U91.12(2B2)
FT4232_WKUP_UART0_RTS_3V3: U37.41(CDBUS3) U91.14(1B2)
FT4232_WKUP_UART0_RX_3V3: U37.38(CDBUS0) U91.13(2B1)
FT4232_WKUP_UART0_TX_3V3: U37.39(CDBUS1) U91.15(1B1)
FT_PWREN#: R243.1 U37.60(~{PWREN})
JTAG_cTI_RTCK: J19.9 R558.1
JTAG_cTI_TCK: J19.11 R495.1 R512.1 U80.1(B) U90.1(B)
JTAG_DIR: R514.2 U87.4(1DIR) U87.5(2DIR)
JTAG_EMU0: J19.13 R560.2 U79.7(B1)
JTAG_EMU1: J19.14 R562.2 U79.6(B2)
JTAG_EMU_RSTn: J19.15 R547.2 ; also on sheet 42
JTAG_TCK: R494.1 R521.1 U87.14(1B2)
JTAG_TDI: J19.3 R535.1 U87.12(2B2)
JTAG_TDIS: J19.4 R563.2
JTAG_TDO: J19.7 U95.7(B1)
JTAG_TMS: J19.1 R530.1 U87.13(2B1)
JTAG_TRST#: J19.2 R517.2 U87.15(1B1)
MCU_UART0_CTS_3V3: U83.9(2A2) ; also on sheet 34
MCU_UART0_RTS_3V3: U83.7(1A2) ; also on sheet 34
MCU_UART0_RX_3V3: U83.8(2A1) ; also on sheet 34
MCU_UART0_TX_3V3: R516.2 U83.6(1A1) ; also on sheet 34
SEL_XDS: U79.5(OE) ; also on sheet 29
SEL_XDS110_INV: J19.8 U80.2(A) U87.1(~{1OE}) U87.16(~{2OE}) U90.2(A) U95.4(~{OE}) ; also on sheet 29
SoC_EMU0: R239.2 U79.2(A1) ; also on sheet 29
SoC_EMU1: R238.2 U79.3(A2) ; also on sheet 29
SoC_TCK: R522.1 ; also on sheet 29
SoC_TDI: U87.9(2A2) ; also on sheet 29
SoC_TDO: U95.2(A1) ; also on sheet 29
SoC_TMS: U87.8(2A1) ; also on sheet 29
SoC_TRST#: U87.6(1A1) ; also on sheet 29
SOC_UART0_RX_3V3: U92.8(2A1) ; also on sheet 42
SOC_UART0_TX_3V3: R554.2 U92.6(1A1) ; also on sheet 42
SOC_UART1_CTS: TP12.1(TP) U96.9(2A2) ; also on sheet 37
SOC_UART1_RTS: TP13.1(TP) U96.7(1A2) ; also on sheet 37
SOC_UART1_RXD: TP9.1(TP) U96.8(2A1) ; also on sheet 37
SOC_UART1_TXD: R566.2 TP10.1(TP) U96.6(1A1) ; also on sheet 37
UART_SHIELD: J17.6(SH1) J17.7(SH2) J17.8(SH3) J17.9(SH4) R242.2
VPHY_3V3_FT4232: C456.2 FL19.1 U37.4(VPHY)
VPLL_3V3_FT4232: C464.2 FL20.1 R251.2 U37.9(VPLL)
WKUP_UART0_CTS_3V3: U91.9(2A2) ; also on sheet 32
WKUP_UART0_RTS_3V3: U91.7(1A2) ; also on sheet 32
WKUP_UART0_RX_3V3: U91.8(2A1) ; also on sheet 32
WKUP_UART0_TX_3V3: R528.2 U91.6(1A1) ; also on sheet 32
N16856152: C157.1 U37.3(OSCO) Y4.2
N16856224: C156.1 U37.2(OSCI) Y4.1
N16857368: C474.2 U94.2(NR/FB)
N16878333: R556.2 U92.5(2DIR)
N16878339: R557.1 U92.4(1DIR)
N16893179: R513.2 U83.5(2DIR)
N16893185: R510.1 U83.4(1DIR)
N16894003: R533.2 U91.5(2DIR)
N16894009: R534.1 U91.4(1DIR)
N16994873: R494.2 U80.4(Y)
N16994875: R558.2 U90.4(Y)
N16995245: C444.1 R512.2
N17378539: LD10.1(CATHODE) R243.2
N18571509: R564.2 U96.5(2DIR)
N18571515: R561.1 U96.4(1DIR)
N19806973: R522.2 U87.7(1A2)

Not connected (* = marked no-connect by the designer): J17 4(ID)*; J19 17* 18* 19*; U35 2(NC)*; U37 18(ADBUS2)* 19(ADBUS3)* 21(ADBUS4)* 22(ADBUS5)* 23(ADBUS6)* 24(ADBUS7)* 30(BDBUS4)* 32(BDBUS5)* 33(BDBUS6)* 34(BDBUS7)* 36(~{SUSPEND})* 43(CDBUS4)* 44(CDBUS5)* 45(CDBUS6)* 46(CDBUS7)* 55(DDBUS4)* 57(DDBUS5)* 58(DDBUS6)* 59(DDBUS7)*; U86 6(NC1)* 7(NC2)*; U94 5(NC)*

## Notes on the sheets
sheet 30
- cTI20 JTAG BUFFERS
- JTAG 20 PIN cTI CONNECTOR
- D-Note :-
  Place pulls on the JTAG signals near to the SoC
  Refer SoC data sheet for Pin Connectivity
  Requirements
- JTAG_DIR = H: A -> B
  JTAG_DIR = L: B -> A
  OE = H: output = Hi-Z
- CAD NOTE: Buffers U99 and U101
  need to be placed closer to the
  cTI-20pin connector J11 to reduce Stub length of the JTAG signals.
- Silk: cTI
- D-Note :-
  TRSTn is the reset to the JTAG
  logic.  For normal operation,
  this is pulled low, and thus
  the JTAG remains in reset as it
  is not being used. When a JTAG
  pod is connected, the pod will
  eventually drive this signal
  high to release the JTAG logic
  from reset and enable a JTAG
  connection.
- D-Note :-
  Add an external ESD protection to
  provide system level ESD protection
  when external connector is used for
  debug. Follow the connectivity table
  for connecting the required pulls
  for the SOC JTAG interface
  Add Test points, and external  ESD
  protection when JTAG connector is
  not used.
- JTAG CLOCK BUFFER
- It should be connected to PORz of the SoC TBD
sheet 31
- FT4232 UART
- Silk: UART
- 90E
- D-Note :-
  Follow SK-AM62P-LP for latest
  FT4232 implementations
- D-Note :- Add a
  filter cap (0.1uF)
- FT4232: 5V to 3.3V@500mA LDO
- SILK SCREEN : SOC_UART1
  TXD
  RTS
  RXD
  CTS
- EEPROM
- R-Note :-
  Verify the implementation with
  the device manufacturer
